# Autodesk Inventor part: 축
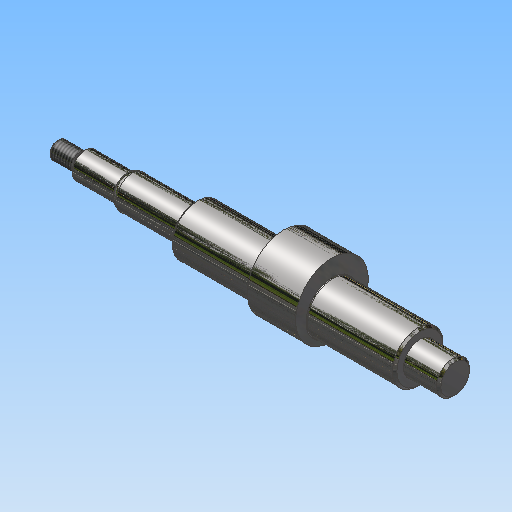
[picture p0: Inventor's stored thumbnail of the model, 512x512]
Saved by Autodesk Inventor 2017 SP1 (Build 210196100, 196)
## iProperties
Created: 2015-12
Part Number: 축
Document SubType Name: Modeling
Designer: mdu
Density: 7.86 g/cm^3
Material: 강철, 연강
Mass: 494.669 g
Surface Area: 129.298 cm^2
Volume: 62.935 cm^3
Appearance: 반광택
Author: mdu
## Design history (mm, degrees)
sketch "스케치1"
  geometry: L1 (62, 100.9)-(62, 67.1) reference; L2 (51, 101.2)-(51, 84) reference; L3 (-51, 84)-(-51, 101.2) reference; L4 (-62, 67.1)-(-62, 100.9) reference; L5 (-51.6, 91.5)-(-61.4, 91.5) reference; L6 (51.6, 91.5)-(61.4, 91.5) reference; L7 (67, 84)-(-114, 84); L8 (-77, 64.201)-(-77, 103.799) reference; L9 (67, 84)-(67, 91.5); L10 (67, 91.5)-(51, 91.5); L11 (51, 91.5)-(51, 95.5); L12 (51, 95.5)-(-51, 95.5); L13 (-51, 95.5)-(-51, 91.5); L14 (-51, 91.5)-(-82, 91.5); L15 (-82, 91.5)-(-82, 90); L16 (-82, 90)-(-102, 90); L17 (-102, 90)-(-102, 87); L18 (-103.5, 88)-(-114, 88); L19 (-114, 88)-(-114, 84); L20 (-102, 87)-(-103.5, 87); L21 (-103.5, 87)-(-103.5, 88); 2 further points
  constraints: 32 end point, 7 parallel, 6 point on line, 5 perpendicular, 2 collinear, 2 horizontal, 1 midpoint, 4 other
  dimensions: "d0" = 5 distance from line of L7.start L1; "d2" = 5 distance between parallel lines of L15 L8; "d3" = 23 diameter of L12 L7; "d4" = 12 diameter of L16 L7; "d5" = 1.5 distance of L17.end L20.end; "d6" = 6 diameter of L20 L7; "d7" = 20 distance of L15.end L16.end; "d8" = 12 distance between parallel lines of L17 L19; "d9" = 8 diameter of L18 L7
revolve "회전1" sketch "스케치1" stored, may be unused: angle "d10" = 90 deg
sketch "스케치2"
  geometry: C1 r 11.5 at (84, 0) reference; C2 r 11.5 at (84, 0) reference; C3 r 16.5 at (87, 0); 1 further point
  constraints: 1 centre point, 1 horizontal alignment
  dimensions: "d11" = 33 diameter of C3; "d12" = 3 distance of C3.centre C1.centre
extrude "돌출1" join sketch "스케치2" stored distance "d13" = 22; taper "d14" = 0 deg
chamfer "모따기1" distance "d15" = 1; stored, may be unused: second distance "d16" = 2, angle "d17" = 45 deg
feature "스레드1" dims "d18" = 10, "d19" = 0
node "작업 평면1"
sketch "스케치3"
  geometry: L1 (-5, -2)-(3, -2); L2 (3, 2)-(-5, 2); L3 (-10, -5)-(-10, 5) reference; A1 r 2 centre (3, 0) between (3, -2) and (3, 2); A2 r 2 centre (-5, 0) between (-5, 2) and (-5, -2); 2 further points
  constraints: 4 end point, 4 point on circle, 4 tangent, 2 centre point, 1 horizontal, 1 horizontal alignment, 1 midpoint, 1 parallel
  dimensions: "d20" = 4 distance between parallel lines of L1 L2; "d21" = 12 dimension on A1 A2; "d22" = 3 distance edge to line of A2 L3
extrude "돌출2" cut sketch "스케치3" distance "d23" = 2.5; taper "d24" = 0 deg
fillet "모깎기1" dims "d25" = 0.3
fillet "모깎기2" dims "d26" = 3
node "솔리드1"
node "참조1"
node "참조2"
node "참조3"
node "참조4"
node "참조5"
node "투영된 루프1"
